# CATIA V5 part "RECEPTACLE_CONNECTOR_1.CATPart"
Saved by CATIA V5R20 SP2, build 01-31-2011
Part number: RECEPTACLE_CONNECTOR_1
Revision: ---
Publications: "MasterKeywayAxis", "InsertFrontFace", "InsertRearFace", "Logical Termination.1", "Logical Pin.1", "CCP", "Face_generated(CCP)", "Face_generated(CCP).1", "BCP", "BCPRPoint_generated(BCP)", "BCPPlane_generated(BCP)", "CaCP", "Face_generated(CaCP)", "Face_generated(CaCP).1", "BaCP", "Face_generated(BaCP)", "Face_generated(BaCP).1", "Axis_generated(CaCP)", "Axis_generated(BaCP)", "Axis_generated(CCP)"
Bounding box of the stored display mesh (mm): x 0 to 34.925, y -17.056 to 17.056, z -17.056 to 17.056
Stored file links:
  C:\Users\ajc8720\Documents\BOEING_WORK\0001-2CES\004-AP242\Boeing-Generic_Harness_R3\RECEPTACLE_CONNECTOR_1.CATPart
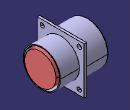
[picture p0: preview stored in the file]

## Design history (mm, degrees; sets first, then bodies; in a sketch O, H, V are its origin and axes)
Parameters
  PartNumber = "RECEPTACLE_CONNECTOR_1"
AxisSystem1 "MasterKeywayAxis": origin (0, 0, 0), X (1, 0, 0), Y (0, 1, 0), Z (0, 0, 1)
Set1 "EGF"
  Set2 "BCP"
    Plane1 "BCPPlane": type Offset, RefPlane face of Pad5, Offset 0, reversed
    Point1 "BCPRPoint": type OnPlane, Support Plane1, H 0, V 0, Direction (0, 1, 0)
  Set3 "BaCP"
    Point2 "BaCPRPoint": (36.0934 {= deleted_ShellLength}, 0, 0)
    Plane2: type OffsetPt, RefPlane yz-plane, RefPoint Point2
  Set4 "CCP"
    Point3 "CCPRPoint": (0, 0, 0)
    Plane3: type OffsetPt, RefPlane yz-plane, RefPoint Point3
  Set5 "CaCP"
    Point4 "CaCPRPoint": type Center, Curve edge [face of Pad1 | face of Pad3]
    Plane4: type OffsetPt, RefPlane yz-plane, RefPoint Point4
Body1 "Shell" (main body)
  Sketch1 on yz-plane, origin (0, 0, 0), H (0, 1, 0), V (0, 0, 1)
    circle A1 centre (0, 0) radius 15.0876
    radius A1 = 15.0876
  Pad1 "ShellFront": profile Sketch1, direction (1, 0, 0), length 18.2372 {= deleted_FlangeFront}
  Sketch2 on zx-plane, origin (0, 0, 0), H (-1, 0, 0), V (0, 0, 1)
    line L1 (0, 14.3637) -> (-0.7874, 14.3637)
    point P2 (-0.7874, 14.3637)
    line L2 (-0.7874, 14.3637) -> (-0.7874, 14.3637)
    line L3 (-0.7874, 15.0876) -> (0, 15.0876)
    line L4 (0, 15.0876) -> (0, 14.3637)
    line L5 (-0.7874, 15.0876) -> (-0.7874, 14.3637)
    point P6 (-0.7874, 14.3637)
    distance L1 H = 14.3637
    distance L3 L1 = 0.7239
    distance L5 L4 = 0.7874
    horizontal: L1 H, L3 H
    vertical: L2 V, L4 V, L5 V
    coincidence: V L4, L5 P2, P6 P2
  Groove1 "ShellFrontRelief": profile Sketch2, axis Sketch2.H, angle 360
  Sketch3 on face of Pad1, origin (18.2372, 0, 0), H (0, 1, 0), V (0, 0, 1)
    circle A1 centre (0, 0) radius 13.6144
    radius A1 = 13.6144
  Pad2 "ShellRear": profile Sketch3, direction (1, 0, 0), length 17.8562 {= deleted_ShellLength - deleted_FlangeFront}
  Sketch4 on zx-plane, origin (0, 0, 0), H (-1, 0, 0), V (0, 0, 1)
    line L1 (-36.0934, 12.2174) -> (-33.8074, 12.2174)
    line L2 (-33.8074, 12.2174) -> (-33.8074, 13.6144)
    line L3 (-33.8074, 13.6144) -> (-36.0934, 13.6144)
    line L4 (-36.0934, 13.6144) -> (-36.0934, 12.2174)
    distance L2 V = 33.8074
    distance L1 H = 12.2174
    distance L4 L2 = 2.286
    distance L3 L1 = 1.397
    horizontal: L1 H, L3 H
    vertical: L2 V, L4 V
  Groove2 "ShellRearRelief": profile Sketch4, axis Sketch4.H, angle 360
  Sketch5 on yz-plane, origin (0, 0, 0), H (0, 1, 0), V (0, 0, 1)
    line L1 (-17.0561, -17.0561) -> (17.0561, -17.0561)
    line L2 (17.0561, -17.0561) -> (17.0561, 17.0561)
    line L3 (17.0561, 17.0561) -> (-17.0561, 17.0561)
    line L4 (-17.0561, 17.0561) -> (-17.0561, -17.0561)
    circle A1 centre (0, 0) radius 13.6144
    point P5 (12.3649, 14.6099)
    line L5 (12.3649, 14.6099) -> (12.3649, 14.6099)
    point P6 (12.3649, 14.6099)
    arc A2 centre (13.4874, 13.4874) radius 1.5875 from (12.3649, 14.6099) to (14.6099, 12.3649) cw
    point P7 (13.4874, 13.4874)
    point P8 (14.6099, 12.3649)
    line L6 (14.6099, 12.3649) -> (14.6099, 12.3649)
    point P9 (14.6099, 12.3649)
    arc A3 centre (13.4874, 13.4874) radius 1.5875 from (14.6099, 12.3649) to (12.3649, 14.6099) cw
    point P10 (13.4874, 13.4874)
    construction line L7 (0, 0) -> (16.5549, 16.5549)
    point P12 (14.6099, -12.3649)
    point P13 (14.6099, -12.3649)
    line L8 (14.6099, -12.3649) -> (14.6099, -12.3649)
    point P14 (12.3649, -14.6099)
    arc A4 centre (13.4874, -13.4874) radius 1.5875 from (14.6099, -12.3649) to (12.3649, -14.6099) ccw
    point P16 (12.3649, -14.6099)
    line L9 (12.3649, -14.6099) -> (12.3649, -14.6099)
    arc A5 centre (13.4874, -13.4874) radius 1.5875 from (12.3649, -14.6099) to (14.6099, -12.3649) ccw
    point P18 (-14.6099, -12.3649)
    point P19 (-14.6099, -12.3649)
    line L10 (-14.6099, -12.3649) -> (-14.6099, -12.3649)
    point P20 (-12.3649, -14.6099)
    arc A6 centre (-13.4874, -13.4874) radius 1.5875 from (-14.6099, -12.3649) to (-12.3649, -14.6099) cw
    point P22 (-12.3649, -14.6099)
    line L11 (-12.3649, -14.6099) -> (-12.3649, -14.6099)
    arc A7 centre (-13.4874, -13.4874) radius 1.5875 from (-12.3649, -14.6099) to (-14.6099, -12.3649) cw
    point P24 (-12.3649, 14.6099)
    point P25 (-14.6099, 12.3649)
    arc A8 centre (-13.4874, 13.4874) radius 1.5875 from (-14.6099, 12.3649) to (-12.3649, 14.6099) ccw
    point P27 (-12.3649, 14.6099)
    line L12 (-12.3649, 14.6099) -> (-12.3649, 14.6099)
    point P28 (-14.6099, 12.3649)
    arc A9 centre (-13.4874, 13.4874) radius 1.5875 from (-12.3649, 14.6099) to (-14.6099, 12.3649) ccw
    line L13 (-14.6099, 12.3649) -> (-14.6099, 12.3649)
    distance H P7 = 13.4874
    length L3 = 34.1122
    length L2 = 34.1122
    radius A2 = 1.5875
    radius A1 = 13.6144
    angle L7 H = 45
    horizontal: L1 H, L3 H
    vertical: L2 V, L4 V
    symmetry: L2 L4 V, L3 L1 H, L5 L6 L7, P9 P12 H, P8 P13 H, L6 L8 H, P5 P14 H, A3 A4 H, P6 P16 H, L5 L9 H, A2 A5 H, P12 P18 V, P13 P19 V, L8 L10 V, P14 P20 V, A4 A6 V, P16 P22 V, L9 L11 V, A5 A7 V, P5 P24 V, P9 P25 V, A3 A8 V, P6 P27 V, L5 L12 V, P8 P28 V, A2 A9 V, L6 L13 V
    tangency: A2 L5, L6 A2, A3 L5, A3 L6
    coincidence: P7 L7, P10 L7
    parallelism: L6 L7
  Pad3 "MountingFlange": profile Sketch5, direction (1, 0, 0), length 19.9898 {= deleted_FlangeFront + deleted_FlangeThickness}, opposite side length -18.2372 {= -( deleted_FlangeFront )}
  Sketch6 on yz-plane, origin (0, 0, 0), H (0, 1, 0), V (0, 0, 1)
    arc A1 centre (0, 0) radius 12.7254 from (-1.5875, 12.626) to (1.5875, 12.626) ccw
    line L1 (1.5875, 12.626) -> (1.5875, 13.3096)
    line L2 (1.5875, 13.3096) -> (-1.5875, 13.3096)
    line L3 (-1.5875, 13.3096) -> (-1.5875, 12.626)
    radius A1 = 12.7254
    distance L1 L3 = 3.175
    distance H L2 = 13.3096
    horizontal: L2 H
    vertical: L1 V, L3 V
    symmetry: L3 L1 V
  Pocket1 "ShellFrontID": profile Sketch6, direction (1, 0, 0), length 13.716 {= deleted_ShellFrontIDLength}
  Sketch7 on face of Pad2, origin (36.0934, 0, 0), H (0, 1, 0), V (0, 0, 1)
    point P1 (0, 0)
    reference intersected line E1 through (0, 0) direction (0, 1) from zx-plane
    reference intersected line E2 through (0, 0) direction (-1, 0) from xy-plane
    coincidence: P1 E1, P1 E2
  Hole1 "ShellRearID": placed by Sketch7, at (36.0934, 0, 0) direction (-1, 0, 0), diameter 25.908 {= deleted_ShellRearID}, depth 22.3774 {= deleted_ShellLength - deleted_ShellFrontIDLength}
Body2 "Insert"
  Sketch8 on yz-plane, origin (0, 0, 0), H (0, 1, 0), V (0, 0, 1)
    circle A1 centre (0, 0) radius 11.0109
    radius A1 = 11.0109
  Pad4 "FrontInsertPad": profile Sketch8, direction (1, 0, 0), length 22.225 {= deleted_InsertFront + deleted_InsertLength - deleted_GrommetLength}, opposite side length -2.3622 {= -( deleted_InsertFront )}
  Sketch9 on yz-plane, origin (0, 0, 0), H (0, 1, 0), V (0, 0, 1)
    circle A1 centre (0, 0) radius 11.4554
    radius A1 = 11.4554
  Pad5 "RearInsertPad": profile Sketch9, direction (1, 0, 0), length 34.925 {= deleted_InsertFront + deleted_InsertLength}, opposite side length -22.225 {= -( deleted_InsertFront + deleted_InsertLength - deleted_GrommetLength )}
Body3 "CCP"
  Sketch10 on face of Pad1, origin (0, 0, 0), H (0, -1, 0), V (0, 0, 1)
    arc A1 centre (0, 0) radius 1.016 from (-0.672, 0.762) to (0.672, 0.762) ccw
    line L1 (-0.672, 0.762) -> (0.672, 0.762)
    distance L1 H = 0.762
    radius A1 = 1.016
  Sketch11 on face of Pad1, origin (0, 0, 0), H (0, -1, 0), V (0, 0, 1)
    circle A1 centre (0, 0) radius 1.27
    radius A1 = 1.27
  Pad6: profile Sketch11, direction (-1, 0, 0), length 0.254, opposite side length 0.254
  Pocket2: profile Sketch10, direction (-1, 0, 0), through (limit type 6)
Body4 "CaCP"
  Sketch12 on face of Pad3, origin (18.2372, 0, 0), H (0, -1, 0), V (0, 0, 1)
    arc A1 centre (0, 0) radius 1.016 from (-0.672, 0.762) to (0.672, 0.762) ccw
    line L1 (-0.672, 0.762) -> (0.672, 0.762)
    distance L1 H = 0.762
    radius A1 = 1.016
  Pad7: profile Sketch12, direction (1, 0, 0), length 0.508
Body5 "BaCP"
  Sketch13 on face of Pad2, origin (36.0934, 0, 0), H (0, 1, 0), V (0, 0, 1)
    arc A1 centre (0, 0) radius 1.016 from (-0.672, 0.762) to (0.672, 0.762) ccw
    line L1 (-0.672, 0.762) -> (0.672, 0.762)
    distance L1 H = 0.762
    radius A1 = 1.016
  Sketch14 on face of Pad2, origin (36.0934, 0, 0), H (0, 1, 0), V (0, 0, 1)
    circle A1 centre (0, 0) radius 1.27
    radius A1 = 1.27
  Pad8: profile Sketch14, direction (1, 0, 0), length 0.254, opposite side length 0.254
  Pocket3: profile Sketch13, direction (1, 0, 0), through (limit type 6)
